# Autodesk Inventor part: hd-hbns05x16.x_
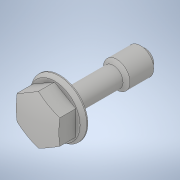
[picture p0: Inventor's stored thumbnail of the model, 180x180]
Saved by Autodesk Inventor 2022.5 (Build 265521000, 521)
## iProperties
Created: 2021-02
Part Number: hd-hbns05x16.x_
Material: 一般
Document SubType Name: Modeling
Designer: ImaoCorp
Density: 1 g/cm^3
Appearance: 既定
Sending System: SOLIDWORKS 2019-2019304
MC: AMD64
MC_MODEL: Intel64 Family 6 Model 60 Stepping 3, GenuineIntel
OS: Windows_NT
FRU: Parasolid Version 31.0, build 290,  9- 1-2019
FORMAT: text
GUISE: transmit
KEY: hd-hbns05x16
FILE: hd-hbns05x16.x_t
DATE: Mon Feb 22 15:01:04 2021
Author: ImaoCorp
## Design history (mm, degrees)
feature "Base1"
node "ソリッド1"
